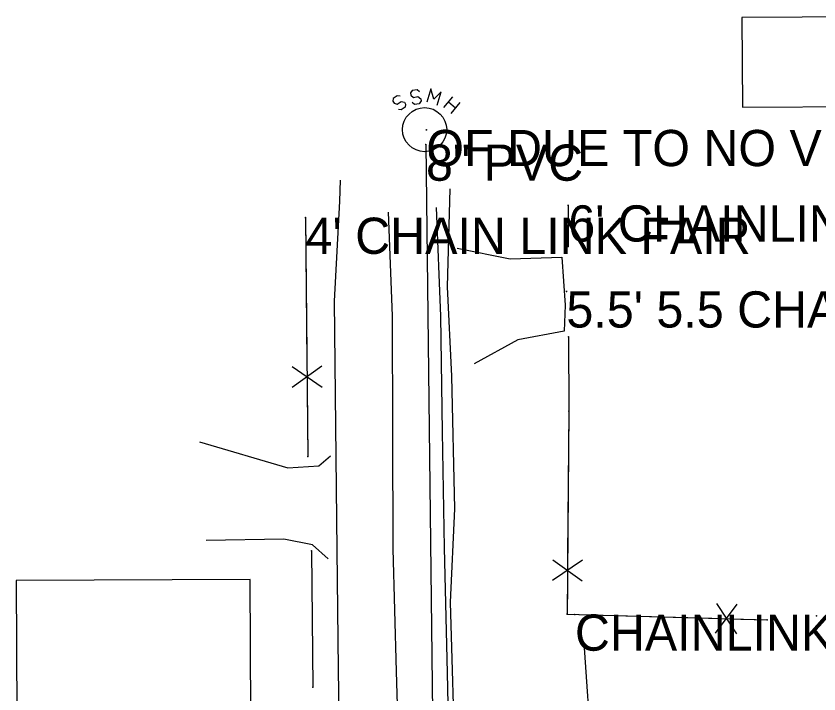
# Model space of a CAD drawing. Extents: x 1304270 to 1306561, y 1876019 to 1876752.
# Drawn here: x 1304924 to 1305034.9, y 1876492.1 to 1876585.8 of the extents above; entities that cross this region are included whole.
import ezdxf

# ---------------------------------------------------------------- set-up
doc = ezdxf.new("R2010")
doc.units = 0
for name, color, linetype in [('S_BUILDING', 7, 'Continuous'), ('S_DITCHLINE', 7, 'Continuous'), ('S_DRIVEWAY', 7, 'Continuous'), ('S_EDGE_PAVEMENT', 7, 'Continuous'), ('S_FENCE', 7, 'Continuous'), ('S_FENCE_ANNOT', 7, 'Continuous'), ('S_GATE_ANNOT', 7, 'Continuous'), ('S_MANHOLE_ANNOT', 7, 'Continuous'), ('S_MSC_PT_SYM', 7, 'Continuous'), ('S_PAVEMENT_CROWN', 7, 'Continuous'), ('S_SANITARY_SEWER', 7, 'Continuous'), ('S_SANITARY_SEWER_ANNOT', 7, 'Continuous'), ('S_SURVEY_TEXT_ANNOT', 7, 'Continuous'), ('S_UTL_PT_SYM', 7, 'Continuous')]:
    doc.layers.add(name, color=color, linetype=linetype)

msp = doc.modelspace()

# ---------------------------------------------------------------- linework, layer by layer
at = {"layer": 'S_BUILDING'}
for points in [[(1305057.49, 1876585.76), (1305024.23, 1876585.56), (1305024.31, 1876573.15), (1305057.56, 1876573.34)], [(1304923.99, 1876507.77), (1304924.26, 1876452.21), (1304956.59, 1876452.37), (1304956.32, 1876507.92)]]:
    msp.add_lwpolyline(points, close=True, dxfattribs=at)
at = {"layer": 'S_DITCHLINE'}
msp.add_lwpolyline([(1304983.88, 1876561.9), (1304983.51, 1876548.33), (1304984.11, 1876535.99), (1304984.55, 1876517.68), (1304983.92, 1876504.78), (1304984.62, 1876481.18), (1304985.32, 1876457.57), (1304985.05, 1876445.87), (1304984.88, 1876440.02), (1304985.87, 1876439.84)], dxfattribs=at)
at = {"layer": 'S_DRIVEWAY'}
for points in [[(1304984.89, 1876553.69), (1304992.23, 1876552.23), (1304999.35, 1876552.42), (1304999.8, 1876545.81), (1304999.66, 1876542.21), (1304993.28, 1876541), (1304987.25, 1876537.7)], [(1304949.34, 1876526.92), (1304961.52, 1876523.34), (1304965.82, 1876523.62), (1304967.42, 1876525.01)], [(1304967.07, 1876510.74), (1304964.93, 1876512.7), (1304960.97, 1876513.48), (1304950.24, 1876513.29)], [(1305002.46, 1876498.47), (1305003.42, 1876484.46), (1305002.97, 1876470.78), (1305005.01, 1876462.25), (1305012.38, 1876447.36), (1305018.95, 1876438.88), (1305021.85, 1876432.89), (1305019.65, 1876427.36)]]:
    msp.add_lwpolyline(points, dxfattribs=at)
at = {"layer": 'S_EDGE_PAVEMENT'}
for points in [[(1304955.71, 1876431.43), (1304958.86, 1876433.29), (1304960.92, 1876434.83), (1304962.4, 1876436.34), (1304963.45, 1876437.84), (1304964.52, 1876439.78), (1304965.28, 1876442.29), (1304965.65, 1876444.07), (1304966.18, 1876448.9), (1304966.95, 1876449.27), (1304967.84, 1876464.15), (1304968.73, 1876479.02), (1304968.52, 1876495.5), (1304968.32, 1876511.97), (1304968.15, 1876529.16), (1304967.98, 1876546.35), (1304968.71, 1876560.16), (1304968.79, 1876563.1)], [(1304983.88, 1876433.76), (1304983.41, 1876439.63), (1304983.58, 1876444.33), (1304983.57, 1876450), (1304983.47, 1876470.67), (1304983.96, 1876477.71), (1304983.55, 1876495.01), (1304983.14, 1876512.3), (1304982.9, 1876528.29), (1304982.66, 1876544.28), (1304982.06, 1876559.3)]]:
    msp.add_lwpolyline(points, dxfattribs=at)
at = {"layer": 'S_FENCE'}
for p, q in [((1305000.25, 1876559.6), (1305000.22, 1876553.93)), ((1304963.97, 1876557.9), (1304964.28, 1876524.92)), ((1305000.27, 1876541.45), (1305000.31, 1876531.17)), ((1304962.11, 1876537.32), (1304966.24, 1876534.49)), ((1304962.11, 1876537.32), (1304966.24, 1876534.49)), ((1304966.21, 1876537.36), (1304962.14, 1876534.45)), ((1304966.21, 1876537.36), (1304962.14, 1876534.45)), ((1305000.31, 1876531.17), (1305000.1, 1876503.14)), ((1304964.8, 1876511.85), (1304964.96, 1876493.05)), ((1305002.2, 1876510.59), (1304998.09, 1876507.75)), ((1305002.2, 1876510.59), (1304998.09, 1876507.75)), ((1304998.11, 1876510.62), (1305002.18, 1876507.72)), ((1304998.11, 1876510.62), (1305002.18, 1876507.72)), ((1305020.6, 1876500.49), (1305023.58, 1876504.5)), ((1305020.6, 1876500.49), (1305023.58, 1876504.5)), ((1305020.72, 1876504.59), (1305023.46, 1876500.41)), ((1305020.72, 1876504.59), (1305023.46, 1876500.41)), ((1305000.1, 1876503.14), (1305027.71, 1876502.33))]:
    msp.add_line(p, q, dxfattribs=at)
for points in [[(1305000.25, 1876559.6), (1305000.22, 1876553.93)], [(1305000.25, 1876559.6), (1305000.22, 1876553.93)], [(1304963.97, 1876557.9), (1304964.16, 1876537.9)], [(1304963.97, 1876557.9), (1304964.16, 1876537.9)], [(1305000.27, 1876541.45), (1305000.31, 1876531.17)], [(1305000.27, 1876541.45), (1305000.31, 1876531.17)], [(1304964.2, 1876533.91), (1304964.28, 1876524.92)], [(1304964.2, 1876533.91), (1304964.28, 1876524.92)], [(1305000.31, 1876531.17), (1305000.16, 1876511.17)], [(1305000.31, 1876531.17), (1305000.16, 1876511.17)], [(1304964.8, 1876511.85), (1304964.96, 1876493.05)], [(1304964.8, 1876511.85), (1304964.96, 1876493.05)], [(1305000.13, 1876507.17), (1305000.1, 1876503.14)], [(1305000.13, 1876507.17), (1305000.1, 1876503.14)], [(1305000.1, 1876503.14), (1305020.09, 1876502.56)], [(1305000.1, 1876503.14), (1305020.09, 1876502.56)], [(1305024.09, 1876502.44), (1305027.71, 1876502.33)], [(1305024.09, 1876502.44), (1305027.71, 1876502.33)]]:
    msp.add_lwpolyline(points, dxfattribs=at)
at = {"layer": 'S_MSC_PT_SYM'}
for points in [[(1305000.25, 1876559.6), (1305000.25, 1876559.65), (1305000.25, 1876559.6), (1305000.2, 1876559.6), (1305000.25, 1876559.6), (1305000.25, 1876559.55), (1305000.25, 1876559.6), (1305000.3, 1876559.6)], [(1304963.97, 1876557.9), (1304963.97, 1876557.95), (1304963.97, 1876557.9), (1304963.92, 1876557.9), (1304963.97, 1876557.9), (1304963.97, 1876557.85), (1304963.97, 1876557.9), (1304964.02, 1876557.9)], [(1305000.22, 1876553.93), (1305000.22, 1876553.98), (1305000.22, 1876553.93), (1305000.17, 1876553.93), (1305000.22, 1876553.93), (1305000.22, 1876553.88), (1305000.22, 1876553.93), (1305000.27, 1876553.93)], [(1304999.99, 1876547.72), (1304999.99, 1876547.77), (1304999.99, 1876547.72), (1304999.94, 1876547.72), (1304999.99, 1876547.72), (1304999.99, 1876547.67), (1304999.99, 1876547.72), (1305000.04, 1876547.72)], [(1305000.27, 1876541.45), (1305000.27, 1876541.5), (1305000.27, 1876541.45), (1305000.22, 1876541.45), (1305000.27, 1876541.45), (1305000.27, 1876541.4), (1305000.27, 1876541.45), (1305000.32, 1876541.45)], [(1305000.31, 1876531.17), (1305000.31, 1876531.22), (1305000.31, 1876531.17), (1305000.26, 1876531.17), (1305000.31, 1876531.17), (1305000.31, 1876531.12), (1305000.31, 1876531.17), (1305000.36, 1876531.17)], [(1304964.28, 1876524.92), (1304964.28, 1876524.97), (1304964.28, 1876524.92), (1304964.23, 1876524.92), (1304964.28, 1876524.92), (1304964.28, 1876524.87), (1304964.28, 1876524.92), (1304964.33, 1876524.92)], [(1304964.8, 1876511.85), (1304964.8, 1876511.9), (1304964.8, 1876511.85), (1304964.75, 1876511.85), (1304964.8, 1876511.85), (1304964.8, 1876511.8), (1304964.8, 1876511.85), (1304964.85, 1876511.85)], [(1305000.1, 1876503.14), (1305000.1, 1876503.19), (1305000.1, 1876503.14), (1305000.05, 1876503.14), (1305000.1, 1876503.14), (1305000.1, 1876503.09), (1305000.1, 1876503.14), (1305000.15, 1876503.14)], [(1305001.17, 1876503.07), (1305001.17, 1876503.12), (1305001.17, 1876503.07), (1305001.12, 1876503.07), (1305001.17, 1876503.07), (1305001.17, 1876503.02), (1305001.17, 1876503.07), (1305001.22, 1876503.07)], [(1305027.71, 1876502.33), (1305027.71, 1876502.38), (1305027.71, 1876502.33), (1305027.66, 1876502.33), (1305027.71, 1876502.33), (1305027.71, 1876502.28), (1305027.71, 1876502.33), (1305027.76, 1876502.33)], [(1305034.53, 1876502.88), (1305034.53, 1876502.93), (1305034.53, 1876502.88), (1305034.48, 1876502.88), (1305034.53, 1876502.88), (1305034.53, 1876502.83), (1305034.53, 1876502.88), (1305034.58, 1876502.88)], [(1304964.96, 1876493.05), (1304964.96, 1876493.1), (1304964.96, 1876493.05), (1304964.91, 1876493.05), (1304964.96, 1876493.05), (1304964.96, 1876493), (1304964.96, 1876493.05), (1304965.01, 1876493.05)]]:
    msp.add_lwpolyline(points, dxfattribs=at)
at = {"layer": 'S_PAVEMENT_CROWN'}
msp.add_lwpolyline([(1304975.11, 1876431.43), (1304976.15, 1876450.01), (1304976.59, 1876464.12), (1304977.03, 1876478.23), (1304976.54, 1876495.18), (1304976.06, 1876512.13), (1304976.01, 1876528.24), (1304975.96, 1876544.34), (1304975.42, 1876558.64)], dxfattribs=at)
at = {"layer": 'S_SANITARY_SEWER'}
for p, q in [((1304976.08, 1876574.37), (1304976, 1876573.98)), ((1304976.62, 1876574.75), (1304976.08, 1876574.37)), ((1304977.05, 1876574.68), (1304976.62, 1876574.75)), ((1304983.05, 1876573.13), (1304984.29, 1876574.6)), ((1304976, 1876573.98), (1304976.2, 1876573.71)), ((1304976.2, 1876573.71), (1304976.62, 1876573.59)), ((1304976.62, 1876573.59), (1304977.16, 1876573.94)), ((1304977.16, 1876573.94), (1304977.63, 1876573.86)), ((1304977.71, 1876573.17), (1304977.16, 1876572.78)), ((1304977.63, 1876573.86), (1304977.78, 1876573.59)), ((1304977.78, 1876573.59), (1304977.71, 1876573.17)), ((1304983.71, 1876573.9), (1304984.68, 1876573.09)), ((1304985.26, 1876573.79), (1304984.02, 1876572.31)), ((1304977.16, 1876572.78), (1304976.78, 1876572.86)), ((1304980.6, 1876568), (1304982.29, 1876417.14))]:
    msp.add_line(p, q, dxfattribs=at)
for points in [[(1304979.72, 1876575.3), (1304979.37, 1876575.57), (1304978.71, 1876575.49), (1304978.48, 1876575.14), (1304978.52, 1876574.83), (1304978.87, 1876574.52), (1304979.49, 1876574.64), (1304979.88, 1876574.33), (1304979.92, 1876574.02), (1304979.64, 1876573.63), (1304979.02, 1876573.55), (1304978.68, 1876573.82)], [(1304982.16, 1876573.44), (1304982.71, 1876575.3), (1304981.66, 1876574.29), (1304981.27, 1876575.72), (1304980.73, 1876573.86)]]:
    msp.add_lwpolyline(points, dxfattribs=at)
msp.add_circle((1304980.41, 1876570.06), 3.05, dxfattribs=at)
at = {"layer": 'S_UTL_PT_SYM'}
for points in [[(1304980.65, 1876570.02), (1304980.65, 1876570.07), (1304980.65, 1876570.02), (1304980.6, 1876570.02), (1304980.65, 1876570.02), (1304980.65, 1876569.97), (1304980.65, 1876570.02), (1304980.7, 1876570.02)], [(1304980.6, 1876568), (1304980.6, 1876568.05), (1304980.6, 1876568), (1304980.55, 1876568), (1304980.6, 1876568), (1304980.6, 1876567.95), (1304980.6, 1876568), (1304980.65, 1876568)]]:
    msp.add_lwpolyline(points, dxfattribs=at)

# ---------------------------------------------------------------- texts
at = {"layer": 'S_FENCE_ANNOT'}
for s, p in [("6' CHAINLINK/3 BARB FAIR", (1305000.25, 1876554.6)), ("4' CHAIN LINK FAIR", (1304963.97, 1876552.9))]:
    msp.add_text(s, height=5, dxfattribs=at).set_placement(p)
at = {"layer": 'S_GATE_ANNOT'}
msp.add_text("5.5' 5.5 CHAINLINK GT 3 BARB FAIR", height=5, dxfattribs=at).set_placement((1304999.99, 1876542.72))
at = {"layer": 'S_MANHOLE_ANNOT'}
msp.add_text('OF DUE TO NO VISIBILITY', height=5, dxfattribs=at).set_placement((1304980.65, 1876565.02))
at = {"layer": 'S_SANITARY_SEWER_ANNOT'}
msp.add_text('8" PVC', height=5, dxfattribs=at).set_placement((1304980.6, 1876563))
at = {"layer": 'S_SURVEY_TEXT_ANNOT'}
msp.add_text('CHAINLINK FE WITH BARB GT LOCKE', height=5, dxfattribs=at).set_placement((1305001.17, 1876498.07))

doc.saveas('drawing.dxf')
